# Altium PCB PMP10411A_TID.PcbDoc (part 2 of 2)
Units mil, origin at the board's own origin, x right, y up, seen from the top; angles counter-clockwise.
Board outline 3000 x 2000 mil, 4 copper layers (Top Layer, Signal Layer 1, Signal Layer 2, Bottom Layer), stack 63.634 mil thick; 167 components, 63 nets, 404 pads, 19 vias.
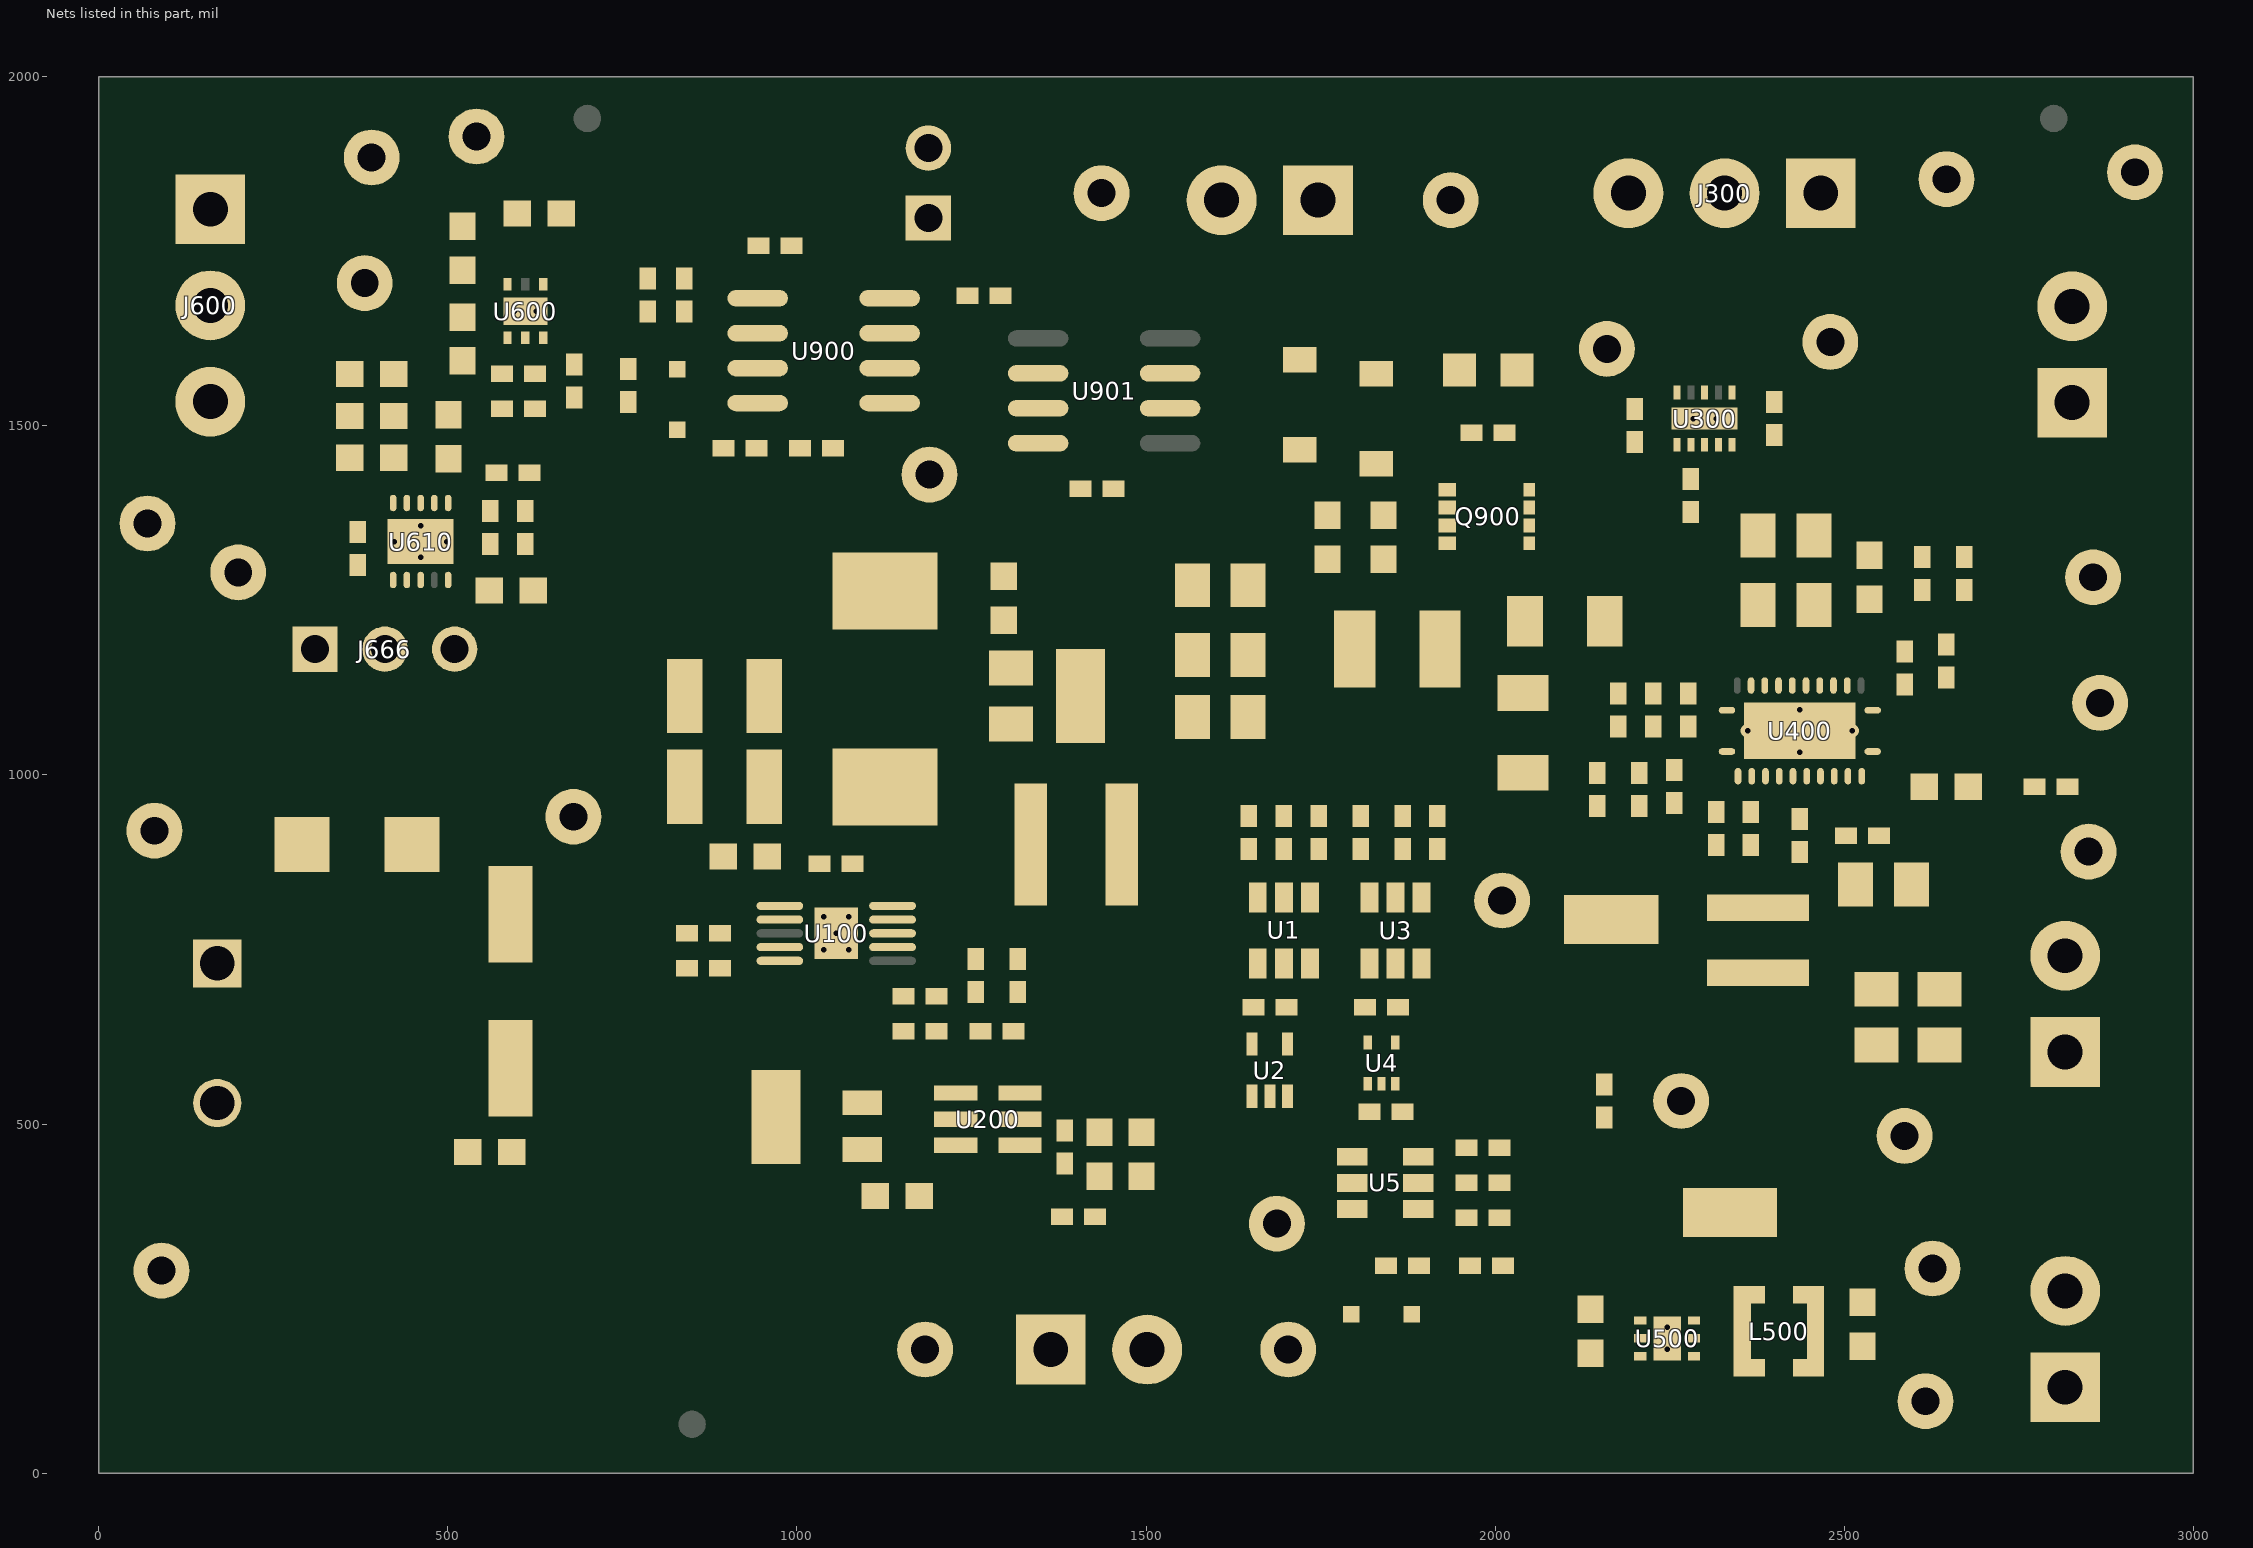
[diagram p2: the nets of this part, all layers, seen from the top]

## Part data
C1 C3 C4 C5 C106 C404 C413 C415 C614: "CAP, CERM, 0.1 µF, 25 V, +/- 10%, X5R, 0402"
C2 C105: "CAP, CERM, 100 pF, 50 V, +/- 5%, C0G/NP0, 0402"
C90: "CAP, AL, 47 µF, 50 V, +/- 20%, 0.68 ohm, SMD"
C100 C101: "CAP, CERM, 10uF, 50V, +/-10%, X7R, 1210"
C102: "CAP, CERM, 0.1uF, 50V, +/-10%, X7R, 0603"
C103: "CAP, CERM, 0.01 µF, 25 V, +/- 10%, X7R, 0402"
C104 C400: "CAP, CERM, 3300 pF, 50 V, +/- 10%, X7R, 0402"
C107 C108 C109 C405 C406 C407 C408 C412: "CAP, CERM, 22 µF, 10 V, +/- 20%, X5R, 0805"
C110: library part 06035A471JAT2A, "CAP, CERM, 470pF, 50V, +/-5%, C0G/NP0, 0603"
C200 C201 C202: "CAP, CERM, 4.7 µF, 10 V, +/- 10%, X5R, 0603"
C300 C301 C302: "CAP, CERM, 2.2 µF, 6.3 V, +/- 20%, X5R, 0402"
C401: "CAP, CERM, 47pF, 25V, +/-5%, C0G/NP0, 0402"
C402: "CAP, CERM, 330 pF, 50 V, +/- 10%, X7R, 0402"
C403 C410: "CAP, CERM, 0.01 µF, 50 V, +/- 10%, X7R, 0402"
C409: "CAP, CERM, 4.7uF, 10V, +/-10%, X5R, 0603"
C414 C500: "CAP, CERM, 4.7 µF, 6.3 V, +/- 20%, X5R, 0603"
C501 C600 C602 C610 C611 C612 C613 C615: "CAP, CERM, 10 µF, 6.3 V, +/- 20%, X5R, 0603"
C601: "CAP, CERM, 22 pF, 50 V, +/- 5%, C0G/NP0, 0402"
C616: "CAP, CERM, 1000 pF, 16 V, +/- 10%, X5R, 0402"
C900 C901 C902 C903: "CAP, CERM, 0.1uF, 50V, +/-20%, X7R, 0402"
C904: "CAP, CERM, 1uF, 10V, +/-10%, X5R, 0402"
D1: "Diode, Schottky, 30 V, 0.2 A, SOD-323"
D90: "Diode, Schottky, 40 V, 3 A, SMA"
D100: "Diode, Schottky, 60 V, 3 A, SMC"
D900: "Diode, Schottky, 30V, 0.2A, SOD-323"
D901 D902: "Diode, Schottky, 30V, 0.5A, SOD-123"
D903: "LED, Red, SMD"
FID1 FID2 FID3: "Fiducial mark.  There is nothing to buy or mount."
H1 H2 H3 H4: "Bumpon, Hemisphere, 0.44 X 0.20, Clear"
J90: "TERMINAL BLOCK 5.08MM VERT 2POS, TH"
J100 J200 J400 J401 J500: "Terminal Block, 6A, 3.5mm Pitch, 2-Pos, TH"
J300 J600: "Terminal Block, 6A, 3.5mm Pitch, 3-Pos, TH"
J666: "Header, 100mil, 3x1, Gold, TH"
J900: "Header, 100mil, 2x1, Gold, TH"
L100: "Inductor, Shielded, Composite, 10 µH, 4.9 A, 0.05 ohm, SMD"
L200: "Inductor, Shielded, Ferrite, 4.7 µH, 0.86 A, 0.168 ohm, SMD"
L400: "Inductor, Shielded, Composite, 3.3uH, 5.5A, 0.026 ohm, SMD"
L500: "Inductor, Shielded Drum Core, Ferrite, 2.2 µH, 1.4 A, 0.11 ohm, SMD"
Q900: "MOSFET, N-CH, 25 V, 60 A, SON 3.3x3.3mm"
R1 R2 R3 R4 R5 R6 R600: "RES, 100 k, 1%, 0.063 W, 0402"
R7: "RES, 110 k, 1%, 0.063 W, 0402"
R8 R9 R101 R103 R402 R404 R405 R407 R610 R611: "RES, 10.0 k, 1%, 0.063 W, 0402"
R90: "RES, 0.22, 1%, 0.1 W, 0603"
R100: "RES, 340 k, 1%, 0.063 W, 0402"
R102: "RES, 31.6 k, 1%, 0.063 W, 0402"
R104: library part CRCW08058R06FKEA, "RES, 8.06 ohm, 1%, 0.125W, 0805"
R200: "RES, 1.82 M, 1%, 0.063 W, 0402"
R201: "RES, 200 k, 1%, 0.063 W, 0402"
R400: "RES, 2.80 k, 1%, 0.063 W, 0402"
R401: "RES, 7.68k ohm, 1%, 0.063W, 0402"
R403: "RES, 84.5 k, 1%, 0.063 W, 0402"
R406: "RES, 12.4 k, 1%, 0.063 W, 0402"
R601: "RES, 392 k, 1%, 0.063 W, 0402"
R666: "RES, 0, 5%, 0.1 W, 0603"
R900: "RES, 8.06k ohm, 1%, 0.063W, 0402"
R901: "RES, 10.0k ohm, 1%, 0.063W, 0402"
R902: "RES, 200k ohm, 1%, 0.063W, 0402"
R903: "RES, 3.3, 5%, 0.5 W, 1210"
R904: "RES, 0.68, 1%, 0.25 W, 1206"
R905: "RES, 10.0, 1%, 0.25 W, 1206"
R906 R907: "RES, 1.00 k, 1%, 0.1 W, 0603"
R908: "RES, 330 ohm, 5%, 0.063W, 0402"
TP1 TP2 TP90 TP402 TP404: "Test Point, Miniature, White, TH"
TP91 TP101 TP201 TP300 TP401 TP405 TP501 TP601 TP610 TP612 TP900: "Test Point, Miniature, Red, TH"
TP92 TP102 TP202 TP302 TP403 TP406 TP502 TP602 TP611: "Test Point, Miniature, Black, TH"
TP100 TP200 TP400 TP500: "Test Point, Miniature, SMT"
TP301: "Test Point, Miniature, Yellow, TH"
U1 U3: "Power Sequencer, 6-pin SOT-23"
U2: "Single 2-Input Positive-OR Gate, DCK0005A"
U4: "Single 2-Input Positive-AND Gate, DRL0005A"
U5: "Low Quiescent Current, Programmable-Delay Supervisory Circuit, DBV0006A"
U100: "Buck Inverting Buck-Boost Step Down Regulator with 3.5 to 42 V Input and 0.8 to 39 V Output, -40 to 150 degC, 10-Pin MSOP-PowerPAD (DGQ), Green (RoHS & no Sb/Br)"
U200: "90% Efficient Synchronous Boost Converter with 600-mA Switch, DDC0006A"
U300: "TPS22968QDMGTQ1, DMG0010A"
U400: "Dual-Output, 3-A, Quiet Supply with Integrated DC-DC Converter and Low-Noise LDO, RHL0024A"
U500: library part TPS62262DRVR, "Buck Step Down Regulator with 2 to 6 V Input and 1.2 V Output, -40 to 85 degC, 6-Pin SON (DRV), Green (RoHS & no Sb/Br)"
U600: "Single Output High PSRR LDO, 200 mA, Adjustable 1.2 to 6.5 V Output, 2.7 to 6.5 V Input, with Low IQ, 6-pin SON (DRV), -40 to 125 degC, Green (RoHS & no Sb/Br)"
U610: "Single Output Automotive LDO, 3 A, 2.3 to 3.5 V Input, with DDR Termination, 10-pin SON (DRC), -40 to 125 degC, Green (RoHS & no Sb/Br)"
U900: "LinCMOS Timer, D0008A"
U901: "DUAL 4-A PEAK HIGH SPEED LOW- SIDE POWER MOSFET DRIVERS, D0008A"

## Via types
v1: diameter 19.68, hole 7.87, Top Layer to Bottom Layer, 19 vias

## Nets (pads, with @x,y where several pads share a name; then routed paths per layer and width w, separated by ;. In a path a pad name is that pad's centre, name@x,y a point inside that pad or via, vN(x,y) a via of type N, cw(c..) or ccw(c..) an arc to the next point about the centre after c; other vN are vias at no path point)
1V2: C501.1 J500.1 L500.2 R905.2 TP501.1 U500.3
1V06: C402.1 C405.1 C406.1 J400.1 L400.2 R400.1 R904.2 TP401.1
1V06_GOOD: R404.2 TP402.1 U400.6
1V8: C301.1 C414.1 C415.2 J401.1 R406.2 TP405.1 U300.5 U400.17 U400.18
1V8_ANALOG: J300.1 TP301.1 U300.6
1V8_VSENSE: C415.1 R406.1 R407.2 U400.16
3V3: C1.2 C3.2 C4.2 C107.1 C108.1 C109.1 C200.1 C300.1 C302.1 C407.1 C408.1 C409.1 C412.1 C413.2 C500.1 C900.1 J100.1 J900.2 L100.2 L200.1 R1.2 R2.2 R3.2 R4.2 R5.2 R6.2 R9.2 R102.2 R404.1 R405.2 R666.1 R900.2 R903.2 TP101.1 U1.1 U2.5 U3.1 U4.5 U5.6 U200.3 U200.6 U300.1 U300.3 U400.8 U400.9 U400.11 U400.19 U400.20 U500.2 U500.5 U900.8
3V3MEM: C600.1 C610.1 J666.3 R666.2 U600.6 U610.10
5V: C201.1 C202.1 C904.1 J200.1 R200.2 TP201.1 U200.5 U901.6
EN_2: R1.1 U1.6 U400.12 U600.4
EN_3: R2.1 U1.5 U300.4
EN_4: R3.1 U1.4 U4.2 U500.4
EN_5: R4.1 U2.2 U3.6 U400.7
EN_6: R5.1 U3.5 U300.2
EN_EXTRA: R6.1 TP2.1 U3.4
GND: C1.1 C2.1 C3.1 C4.1 C5.1 C100.2 C101.2 C102.2 C103.1 C104.1 C105.1 C107.2 C108.2 C109.2 C110.2 C200.2 C201.2 C202.2 C300.2 C301.2 C302.2 C400.1 C401.1 C403.1 C405.2 C406.2 C407.2 C408.2 C409.2 C410.1 C412.2 C413.1 C414.2 C500.2 C501.2 C600.2 C602.2 C610.2 C611.2 C612.2 C613.2 C614.1 C615.2 C616.2 C900.2 C901.2 C902.2 C903.2 C904.2 D1.2 D100.2 J90.2 J100.2 J200.2 J300.2 J400.2 J401.2 J500.2 J600.3 J666.1 Q900.1 Q900.2 Q900.3 R8.1 R90.1 R100.1 R103.1 R201.1 R402.2 R403.1 R407.1 R601.1 R611.1 R901.1 R908.1 TP92.1 TP102.1 TP202.1 TP302.1 TP403.1 TP406.1 TP502.1 TP602.1 TP611.1 U1.2 U2.3 U3.2 U4.3 U5.2 U100.9 U100.11 U200.2 U300.8 U300.11 U400.13 U400.21 U400.22 U400.25 U500.6 U500.7 U600.3 U600.7 U610.4 U610.8 U610.11 U900.1 U901.3
  other v1: 2246.35,177.25 2246.35,208.75 1038.64,749.38 1074.07,749.38 1056.35,773 1038.64,796.62 1074.07,796.62 2436.35,1032.49 2361.55,1063 2511.16,1063 2436.35,1093.51 461.15,1311.55 423.74,1334.19 498.55,1334.19 461.15,1356.83 2283.62,1510 2316.38,1510 595.4,1664.19 626.89,1664.19
NetC2_2: C2.2 D1.1 R7.1 R8.2 U5.5
NetC5_2: C5.2 U5.4
NetC90_2: C90.2 R90.2
NetC103_2: C103.2 U100.4
NetC104_2: C104.2 R101.1
NetC105_2: C105.2 R101.2 U100.8
NetC106_1: C106.1 D100.1 L100.1 R104.2 TP100.1 U100.10
NetC106_2: C106.2 U100.1
NetC110_1: C110.1 R104.1
NetC400_2: C400.2 R401.2
NetC401_2: C401.2 R401.1 U400.1
NetC402_2: C402.2 R400.2 R402.1 U400.24
NetC403_2: C403.2 U400.3
NetC404_1: C404.1 U400.5
NetC404_2: C404.2 L400.1 TP400.1 U400.4
NetC410_2: C410.2 U400.15
NetC601_2: C601.2 R600.1 R601.2 U600.2
NetC614_2: C614.2 TP612.1 U610.6
NetC616_1: C616.1 R610.1 R611.2 U610.1
NetC901_1: C901.1 U900.5
NetC902_1: C902.1 C903.1 D900.1 R902.1 U900.2 U900.6
NetD900_2: D900.2 R900.1 R902.2 U900.7
NetD901_1: D901.1 D902.2 D903.1 U901.7
NetD901_2: D901.2 R906.1
NetD902_1: D902.1 R907.1
NetD903_2: D903.2 R908.2
NetJ666_2: J666.2 U610.7
NetJ900_1: J900.1 R901.2 U900.4
NetL200_2: L200.2 TP200.1 U200.1
NetL500_1: L500.1 TP500.1 U500.1
NetQ900_4: Q900.4 R906.2 R907.2
NetQ900_5: Q900.5 Q900.6 Q900.7 Q900.8 R903.1 R904.1 R905.1
NetR9_1: R9.1 U2.1 U4.1 U5.1
NetR100_2: R100.2 U100.5
NetR102_1: R102.1 R103.2 U100.7
NetR200_1: R200.1 R201.2 U200.4
NetR403_2: R403.2 U400.2
NetR405_1: R405.1 TP404.1 U400.10
NetTP1_1: TP1.1 U5.3
NetTP900_1: TP900.1 U900.3 U901.2 U901.4
NetU1_3: U1.3 U2.4
NetU3_3: U3.3 U4.4
VDD_SHV: J300.3 TP300.1 U300.10
VDDQ: C601.1 C602.1 C615.1 J600.1 R600.2 R610.2 TP601.1 U600.1 U610.2
VIN: C90.1 C100.1 C101.1 C102.1 D90.1 TP91.1 U100.2
VIN_P: D90.2 J90.1 R7.2 TP90.1
VTT: C611.1 C612.1 C613.1 J600.2 TP610.1 U610.3 U610.5
pads on no net: FID1.1 FID2.1 FID3.1 H1.0 H2.0 H3.0 H4.0 U100.3 U100.6 U300.7 U300.9 U400.14 U400.23 U600.5 U610.9 U901.1 U901.5 U901.8

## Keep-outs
Keep-Out Layer:
  lines w20: -10,0 ccw(c0,0) 0,-10 ; -10,0 ccw(c0,0) 0,-10 ; -10,0 -10,2000 ; -10,2000 cw(c0,2000) 0,2010 ; -10,2000 cw(c0,2000) 0,2010 ; 0,-10 3000,-10 ; 0,2010 3000,2010 ; 3000,-10 ccw(c3000,0) 3010,0 ; 3000,-10 ccw(c3000,0) 3010,0 ; 3000,2010 cw(c3000,2000) 3010,2000 ; 3000,2010 cw(c3000,2000) 3010,2000 ; 3010,0 3010,2000
  text ".Layer_Name" at 577,-858.49 h60

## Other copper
Top Layer:
  text ".CopyrightYear" at 532,90 h60
  text "TI" at 808,90 h60
  text "©" at 415,86.48 h105
  text ".Layer_Name" at 577,-858.49 h60
Bottom Layer:
  text "MADE IN U.S." at 1250,86.5 h60
  text "UL94V-0" at 2529.5,86.5 h60
  text ".Layer_Name" at 577,-858.49 h60

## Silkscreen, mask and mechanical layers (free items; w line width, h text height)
Top Overlay:
  text "Dyn Load" at 820,1950 h40
  text "3v3" at 1840,1930 h40
  text "ENABLE" at 880,1880 h40
  text "String" at 1340,1740 h40 r90
  text "VDD_SHV GND 1v8_ana" at 2070,1690 h30
  text "String" at 1830,1600 h40
  text "GND VTT VDDQ" at 320,1470 h40 r90
  text "dyn_clk" at 1270,1450 h30 r90
  text "1v8" at 2820,1390 h40
  text "VTT_REF" at 20,1190 h30
  text "1v8_good" at 2700,1170 h30
  text "VTT cntl DIS__EN" at 60,1080 h30
  text "Vin" at 190,870 h30 r90
  text "complete" at 2000,740 h30 r270
  text "power up" at 2050,740 h30 r270
  text "core good" at 2120,610 h40
  text "1v06" at 2420,510 h30
  text "GND  VIN" at 420,480 h40 r90
  text "external" at 1540,470 h30
  text "1v06core" at 2676.31,468 h40
  text "reset" at 1560,420 h40
  text ".PRJ_Number" at 450,260 h60
  text ".PCB_Rev" at 1050,260 h60
  text "5V" at 1150,40 h60
  text "1v2" at 2410,30 h60
  text "1v2" at 2750,10 h30
  text ".Layer_Name" at 577,-858.49 h60
Bottom Overlay:
  text ".Layer_Name" at 577,-858.49 h60
Top Paste:
  text ".Layer_Name" at 577,-858.49 h60
Bottom Paste:
  text ".Layer_Name" at 577,-858.49 h60
Top Solder:
  text ".Layer_Name" at 577,-858.49 h60
  text ".Layer_Name" at 577,-858.49 h60
Bottom Solder:
  text ".Layer_Name" at 577,-858.49 h60
Drill Guide:
  text ".Layer_Name" at 577,-858.49 h60
M1 Board Outline:
  the board outline again, w10
  text ".Layer_Name" at 577,-858.49 h60
M2 Board Dimensions:
  rectangle: 125,-400 500,-275
  rectangle: 0,-275 125,-150
  lines w7: 0,-275 1000,-275 ; 125,-400 125,-150 ; 250,-400 250,-150 ; 500,-400 500,-150 ; 750,-400 750,-150 ; 0,-400 0,-150 1000,-150 1000,-400 0,-400
  text ".Layer_Name" at 577,-858.49 h60
M3 3D STEP Top:
  text ".Layer_Name" at 577,-858.49 h60
M4 3D STEP Bottom:
  text ".Layer_Name" at 577,-858.49 h60
M5 Assembly Top:
  lines w10: -292,-930.17 6308,-930.17 ; -292,-726.83 6310,-726.83 ; -292,-523.5 -292,-1133.5 3713,-1133.5 6310,-1133.5 6310,-523.5 -291.5,-523.5 -291.5,-1133.5 1284,-1133.5 ; 2173,-1133.5 2173,-523.5 ; 3440,-726.83 3440,-523.5 ; 4280,-726.83 4280,-523.5 ; 4902,-1140 4902,-937.17
  text "COMPONENTS MARKED 'DNP' SHOULD NOT BE POPULATED." at 1153.5,-318.5 h60
  text "ASSEMBLY VARIANT:" at 1153,-434 h60
  text ".VariantName" at 2189,-434 h60
  text "PCB VIEWED FROM TOP SIDE" at -228.5,-655.67 h60
  text "BOARD #:" at 2248,-655.67 h60
  text ".PRJ_Number" at 2793.5,-655.67 h60
  text "REV:" at 3638,-655.67 h60
  text ".PCB_Rev" at 3929.5,-655.67 h60
  text "SVN REV:" at 4476,-655.67 h60
  text ".VersionControl_RevNumber" at 4982,-655.67 h60
  text "PLOT NAME =" at -228.5,-1064.34 h60
  text ".plot_File_Name" at 577,-1064.34 h60
  text "GENERATED    :" at 2250,-1064.34 h60
  text ".Print_Date" at 3119.5,-1064.34 h60
  text ".Print_Time" at 3848.5,-1064.34 h60
  text "TEXAS INSTRUMENTS" at 5113,-1064.34 h60
M6 Assembly Bottom:
  lines w10: -292.5,-727.33 6309.5,-727.33 ; -290.5,-930.67 6309.5,-930.67 ; 1115.5,-1140.5 1115.5,-937.67 ; 1737.5,-727.33 1737.5,-524 ; 2577.5,-727.33 2577.5,-524 ; 3844.5,-1134 3844.5,-524 ; 4733.5,-1134 6309,-1134 6309,-524 -292.5,-524 -292.5,-1134 2304.5,-1134 6309.5,-1134 6309.5,-524
  text "COMPONENTS MARKED 'DNP' SHOULD NOT BE POPULATED." at 6102,-318 h60
  text ".VariantName" at 5058,-434 h60
  text "ASSEMBLY VARIANT:" at 6097,-434 h60
  text ".VersionControl_RevNumber" at 1035.5,-656.17 h60
  text "SVN REV:" at 1541.5,-656.17 h60
  text ".PCB_Rev" at 2088,-656.17 h60
  text "REV:" at 2379.5,-656.17 h60
  text ".PRJ_Number" at 3224,-656.17 h60
  text "BOARD #:" at 3769.5,-656.17 h60
  text "PCB VIEWED FROM BOTTOM SIDE" at 6246,-656.17 h60
  text "TEXAS INSTRUMENTS" at 904.5,-1064.84 h60
  text ".Print_Time" at 2169,-1064.84 h60
  text ".Print_Date" at 2898,-1064.84 h60
  text "GENERATED    :" at 3767.5,-1064.84 h60
  text ".plot_File_Name" at 5440.5,-1064.84 h60
  text "PLOT NAME =" at 6246,-1064.84 h60
M9 Title Sheet:
  drawing of 57 lines, arcs and shapes, not listed
  text "1" at 739.84,8036.5 h70
  text "2" at 3235.5,8036.5 h70
  text "3" at 5724.84,8036.5 h70
  text "4" at 8231.51,8036.5 h70
  text "5" at 10730.5,8036.5 h70
  text "6" at 13235.5,8036.5 h70
  text "A" at -416.5,6893.5 h70
  text "A" at 14383.5,6893.5 h70
  text "B" at -416.5,4513.5 h70
  text "B" at 14383.5,4513.5 h70
  text "C" at -416.5,2138.5 h70
  text "C" at 14383.5,2138.5 h70
  text "PROJECT TITLE:" at 11343.5,277.5 h45
  text ".PRJ_Title" at 11393.5,144.17 h70
  text "DESIGNED FOR:" at 11343.5,-23.5 h45
  text ".PRJ_Customer" at 11393.5,-163.5 h70
  text "D" at -416.5,-231.5 h70
  text "D" at 14383.5,-231.5 h70
  text "FILE NAME:" at 11343.5,-323.5 h45
  text ".PCB_File_Name_No_Path" at 11393.5,-443.5 h70
  text "Texas Instruments (TI) and/or its licensors do not warrant the accuracy or completeness of this specification" at 6374,-605.34 h45
  text "ENGINEER:" at 11343.5,-613.5 h45
  text "LAYOUT BY:" at 12848.5,-613.5 h45
  text "or any information contained therein. TI and/or its licensors do not warrant that this design will meet" at 6329.01,-718 h45
  text ".PRJ_Engineer" at 11393.5,-768.49 h70
  text ".PCB_Layout" at 12899,-768.49 h70
  text "the specifications, will be suitable for your application or fit for any particular purpose, or will operate in" at 6329.01,-830.67 h45
  text ".Layer_Name" at 577,-858.49 h60
  text "ALTIUM DESIGNER VERSION:" at 12848.5,-923.5 h45
  text "an implementation. TI and/or its licensors do not warrant that the design is production worthy. You should" at 6329.01,-943.33 h45
  text "completely validate and test your design implementation to confirm the system functionality for your application." at 6374,-1056 h45
  text ".print_Scale" at 11393.5,-1056.83 h70
  text ".Application_BuildNumber" at 12899,-1056.83 h70
  text "1" at 739.84,-1263.5 h70
  text "2" at 3235.5,-1263.5 h70
  text "3" at 5724.84,-1263.5 h70
  text "4" at 8231.51,-1263.5 h70
  text "5" at 10730.5,-1263.5 h70
  text "6" at 13235.5,-1263.5 h70
M10 Fab Notes:
  drawing of 185 lines, arcs and shapes, not listed
  text "DESIGN INFORMATION" at 12381.02,5910 h60
  text "MIN. TRACK WIDTH:" at 11736.46,5730 h60
  text "8" at 12832.7,5730 h60
  text "MIL" at 12987.46,5730 h60
  text "MIN. CLEARANCE:" at 11736.46,5598 h60
  text "0.2" at 12772.7,5598 h60
  text "mm" at 12987.46,5598 h60
  text "MIN. VIA PAD SIZE:" at 11736.46,5466 h60
  text "24" at 12802.71,5466 h60
  text "MIL" at 12987.46,5466 h60
  text "0.05mm (2MIL)" at 12431.46,5324.29 h60
  text "MINIMUM ANNULAR RING" at 11407.23,5320 h60
  text "EXTERNAL" at 13139.46,5320 h60
  text "PER" at 11607.23,5202 h60
  text "IPC-D-275 CLASS 2 LEVEL C" at 11827.23,5202 h60
  text "MIL, HOLES" at 13315.46,5089.71 h60
  text "+/-" at 12923,5089 h60
  text "+/-" at 13777,5089 h60
  text "REGISTRATION TOLERANCES:" at 11407.23,5084 h60
  text "METAL" at 12607,5084 h60
  text "5" at 13183.2,5084 h60
  text "3" at 14016.2,5084 h60
  text "MIL" at 14132.46,5084 h60
  text "MATERIAL:" at 11332.46,4874.54 h60
  text "FR-4 High Tg" at 12318.9,4734.21 h60
  text "FR-408" at 11753.46,4725.64 h60
  text "X" at 12165.46,4725.64 h60
  text "OTHER" at 13241.46,4725.64 h60
  text "62 MIL (1.6mm) +/-10%" at 12073.56,4562.92 h60
  text "THICKNESS:" at 11407.23,4558.64 h60
  text "X" at 11945.4,4558.64 h60
  text "OTHER" at 13358.46,4558.64 h60
  text "TOLERANCE:" at 11407.23,4400.64 h60
  text "X" at 12246.53,4400.64 h60
  text "ANSI IPC-6012 TYPE 3 CLASS 2" at 12433.48,4400.64 h60
  text "OTHER +/-" at 12433.46,4244.64 h60
  text "BOW & TWIST:" at 11407.23,4087.64 h60
  text "X" at 12246.53,4087.64 h60
  text "ANSI IPC-6012 TYPE 3 CLASS 2" at 12433.48,4087.64 h60
  text "OTHER +/-" at 12433.46,3929.13 h60
  text "DRILLING:" at 11332.46,3790.64 h60
  text "REFERENCE:" at 11407.23,3673.64 h60
  text "X" at 12055.46,3673.64 h60
  text "AS SHOWN" at 12242.46,3673.64 h60
  text "X" at 12956.46,3673.64 h60
  text "NC_DRILL FILES" at 13093.46,3673.64 h60
  text "PTH MIN COPPER THICKNESS:" at 11407.23,3515.64 h60
  text "X" at 12757.46,3515.64 h60
  text "1MIL" at 12894.46,3515.64 h60
  text "OTHER" at 13391.46,3515.64 h60
  text "BOARD FINISH:" at 11332.46,3356.64 h60
  text "SILKSCREEN:" at 11487.68,3238.64 h60
  text "X" at 12436.46,3238.64 h60
  text "TOP" at 12562.46,3238.64 h60
  text "X" at 12946.46,3238.64 h60
  text "BOTTOM" at 13073.46,3238.64 h60
  text "SILKSCREEN COLOR:" at 11487.68,3071.64 h60
  text "X" at 12435.42,3071.64 h60
  text "WHITE" at 12562.46,3071.64 h60
  text "OTHER" at 13073.46,3071.64 h60
  text "SOLDER RESIST COLOR:" at 11487.68,2901.64 h60
  text "X" at 12055.42,2742.44 h60
  text "GREEN" at 12182.46,2742.44 h60
  text "BLUE" at 12773.46,2742.44 h60
  text "OTHER" at 13311.46,2742.44 h60
  text "IMMERSION GOLD (ENIG)" at 12393.46,2553.92 h60
  text "ENEPIG" at 13731,2550.64 h60
  text "SURFACE FINISH:" at 11332.46,2549.64 h60
  text "X" at 12206.51,2549.64 h60
  text "IMM. TIN/SILVER OR EQUIV" at 11662,2392.64 h60
  text "OTHER" at 13093.46,2392.64 h60
  text "ARRAY/PANEL:" at 11332.46,2213.64 h60
  text "CUT AND TRIM PER MECH LAYER 1" at 12393.46,2209.35 h60
  text "N.C. ROUTE" at 12393.46,2057.64 h60
  text "X" at 13072.46,2057.64 h60
  text "V. SCORE" at 13259.46,2057.64 h60
  text "CERTIFICATION:" at 11332.46,1920.64 h60
  text "MATERIALS AND WORKMANSHIP FOR ALL PCBS" at 12057.46,1920.64 h60
  text "TO MEET OR EXCEED THE REQUIREMENTS OF:" at 12057.46,1822.64 h60
  text "X" at 11683.96,1686.13 h60
  text "ANSI IPC-A-600F CLASS ->" at 11822.96,1686.13 h60
  text "X" at 13462.02,1686.13 h60
  text "2" at 13580.96,1686.14 h60
  text "1" at 13265.96,1684.64 h60
  text "3" at 13934.96,1684.64 h60
  text "X" at 11686.02,1526.64 h60
  text "UL 94V-0" at 11822.96,1526.64 h60
  text "X" at 12498.02,1526.64 h60
  text "RoHS" at 12634.96,1526.64 h60
  text "OTHER" at 13279.36,1526.64 h60
  text "PER ORDER" at 13676.42,1526.64 h60
  text "ADDITIONAL REQUIREMENTS:" at 11332.46,1385.64 h60
  text "MICROSECTION:" at 11407.23,1270.64 h60
  text "YES" at 12312.96,1270.64 h60
  text "REQUIRED" at 13174.46,1114.49 h60
  text "BARE BOARD ELEC. TEST:" at 11407.23,1111.64 h60
  text "NONE" at 12712.96,1111.64 h60
  text "X" at 13047.46,1111.64 h60
  text "PER ORDER" at 13766.46,1111.64 h60
  text "MANUFACTURER'S UL:" at 11407.23,954.64 h60
  text "RAIL" at 12572.96,950.35 h60
  text "METAL" at 13064.77,950.35 h60
  text "X" at 13440,950 h60
  text "SILK" at 13576.46,950.35 h60
  text ".Layer_Name" at 577,-858.49 h60
M11 Gerber Information:
  lines w10: -292,-930.17 6308,-930.17 ; -292,-726.83 6310,-726.83 ; -292,-523.5 -292,-1133.5 3713,-1133.5 6310,-1133.5 6310,-523.5 -291.5,-523.5 -291.5,-1133.5 1284,-1133.5 ; 2173,-1133.5 2173,-523.5 ; 3440,-726.83 3440,-523.5 ; 4280,-726.83 4280,-523.5 ; 4902,-1140 4902,-937.17
  text "ALL ARTWORK VIEWED FROM TOP SIDE" at -228.5,-655.67 h60
  text "BOARD #:" at 2248,-655.67 h60
  text ".PRJ_Number" at 2793.5,-655.67 h60
  text "REV:" at 3638,-655.67 h60
  text ".PCB_Rev" at 3929.5,-655.67 h60
  text "SVN REV:" at 4476,-655.67 h60
  text ".VersionControl_RevNumber" at 4982,-655.67 h60
  text "LAYER NAME =" at -228.5,-858.49 h60
  text "PLOT NAME =" at -228.5,-1064.34 h60
  text ".plot_File_Name" at 577,-1064.34 h60
  text "GENERATED    :" at 2250,-1064.34 h60
  text ".Print_Date" at 3119.5,-1064.34 h60
  text ".Print_Time" at 3848.5,-1064.34 h60
  text "TEXAS INSTRUMENTS" at 5113,-1064.34 h60
M12 Stackup:
  text ".Layer_Name" at 577,-858.49 h60
M13 Component Bodies Top:
  text ".Layer_Name" at 577,-858.49 h60
M14 Component Bodies Bottom:
  text ".Layer_Name" at 577,-858.49 h60
M15 Courtyards Top:
  text ".Layer_Name" at 577,-858.49 h60
M16 Courtyards Bottom:
  text ".Layer_Name" at 577,-858.49 h60
Drill Drawing:
  circle w1: c5572.82,3220.77 r24.92
  lines w1: 5547.91,2747.35 5572.82,2759.81 5597.74,2747.35 5585.28,2772.27 5597.74,2797.18 5572.82,2784.72 5547.91,2797.18 5560.37,2772.27 5547.91,2747.35 ; 5547.91,2909.31 5560.37,2909.31 5572.82,2896.85 5585.28,2909.31 5597.74,2909.31 5585.28,2921.77 5597.74,2934.22 5585.28,2934.22 5572.82,2946.68 5560.37,2934.22 5547.91,2934.22 5560.37,2921.77 5547.91,2909.31 ; 5547.91,3096.18 5597.74,3096.18 5572.82,3046.35 5547.91,3096.18
  lines w12: 5480,2702.5 7598.44,2702.5 ; 5480,3300.5 7598.44,3300.5 ; 5850.51,2553 5850.51,3450 ; 6207.67,2553 6207.67,3450 ; 6869.15,2553 6869.15,3450 ; 7153.35,2553 7153.35,3450 ; 5480,2553 7598.44,2553 7598.44,3450 5480,3450 5480,2553
  text "Symbol" at 5569.7,3345.35 h72
  text "Quantity" at 5895.36,3345.35 h72
  text "Finished Hole Size" at 6252.52,3345.35 h72
  text "Plated" at 6914,3345.35 h72
  text "Hole Type" at 7198.2,3345.35 h72
  text "19" at 5895.36,3195.85 h60
  text "7.87mil (0.200mm)" at 6252.52,3195.85 h60
  text "PTH" at 6914,3195.85 h60
  text "Round" at 7198.2,3195.85 h60
  text "31" at 5895.36,3046.35 h60
  text "40.00mil (1.016mm)" at 6252.52,3046.35 h60
  text "PTH" at 6914,3046.35 h60
  text "Round" at 7198.2,3046.35 h60
  text "2" at 5895.36,2896.85 h60
  text "49.21mil (1.250mm)" at 6252.52,2896.85 h60
  text "PTH" at 6914,2896.85 h60
  text "Round" at 7198.2,2896.85 h60
  text "16" at 5895.36,2747.35 h60
  text "50.00mil (1.270mm)" at 6252.52,2747.35 h60
  text "PTH" at 6914,2747.35 h60
  text "Round" at 7198.2,2747.35 h60
  text "68 Total" at 5895.36,2597.85 h60
  text ".Layer_Name" at 577,-858.49 h60

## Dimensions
0,0 to 3000,0 on M2 Board Dimensions
0,0 to 0,2000 on M2 Board Dimensions
0,-400 to 1000,-400 on M2 Board Dimensions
